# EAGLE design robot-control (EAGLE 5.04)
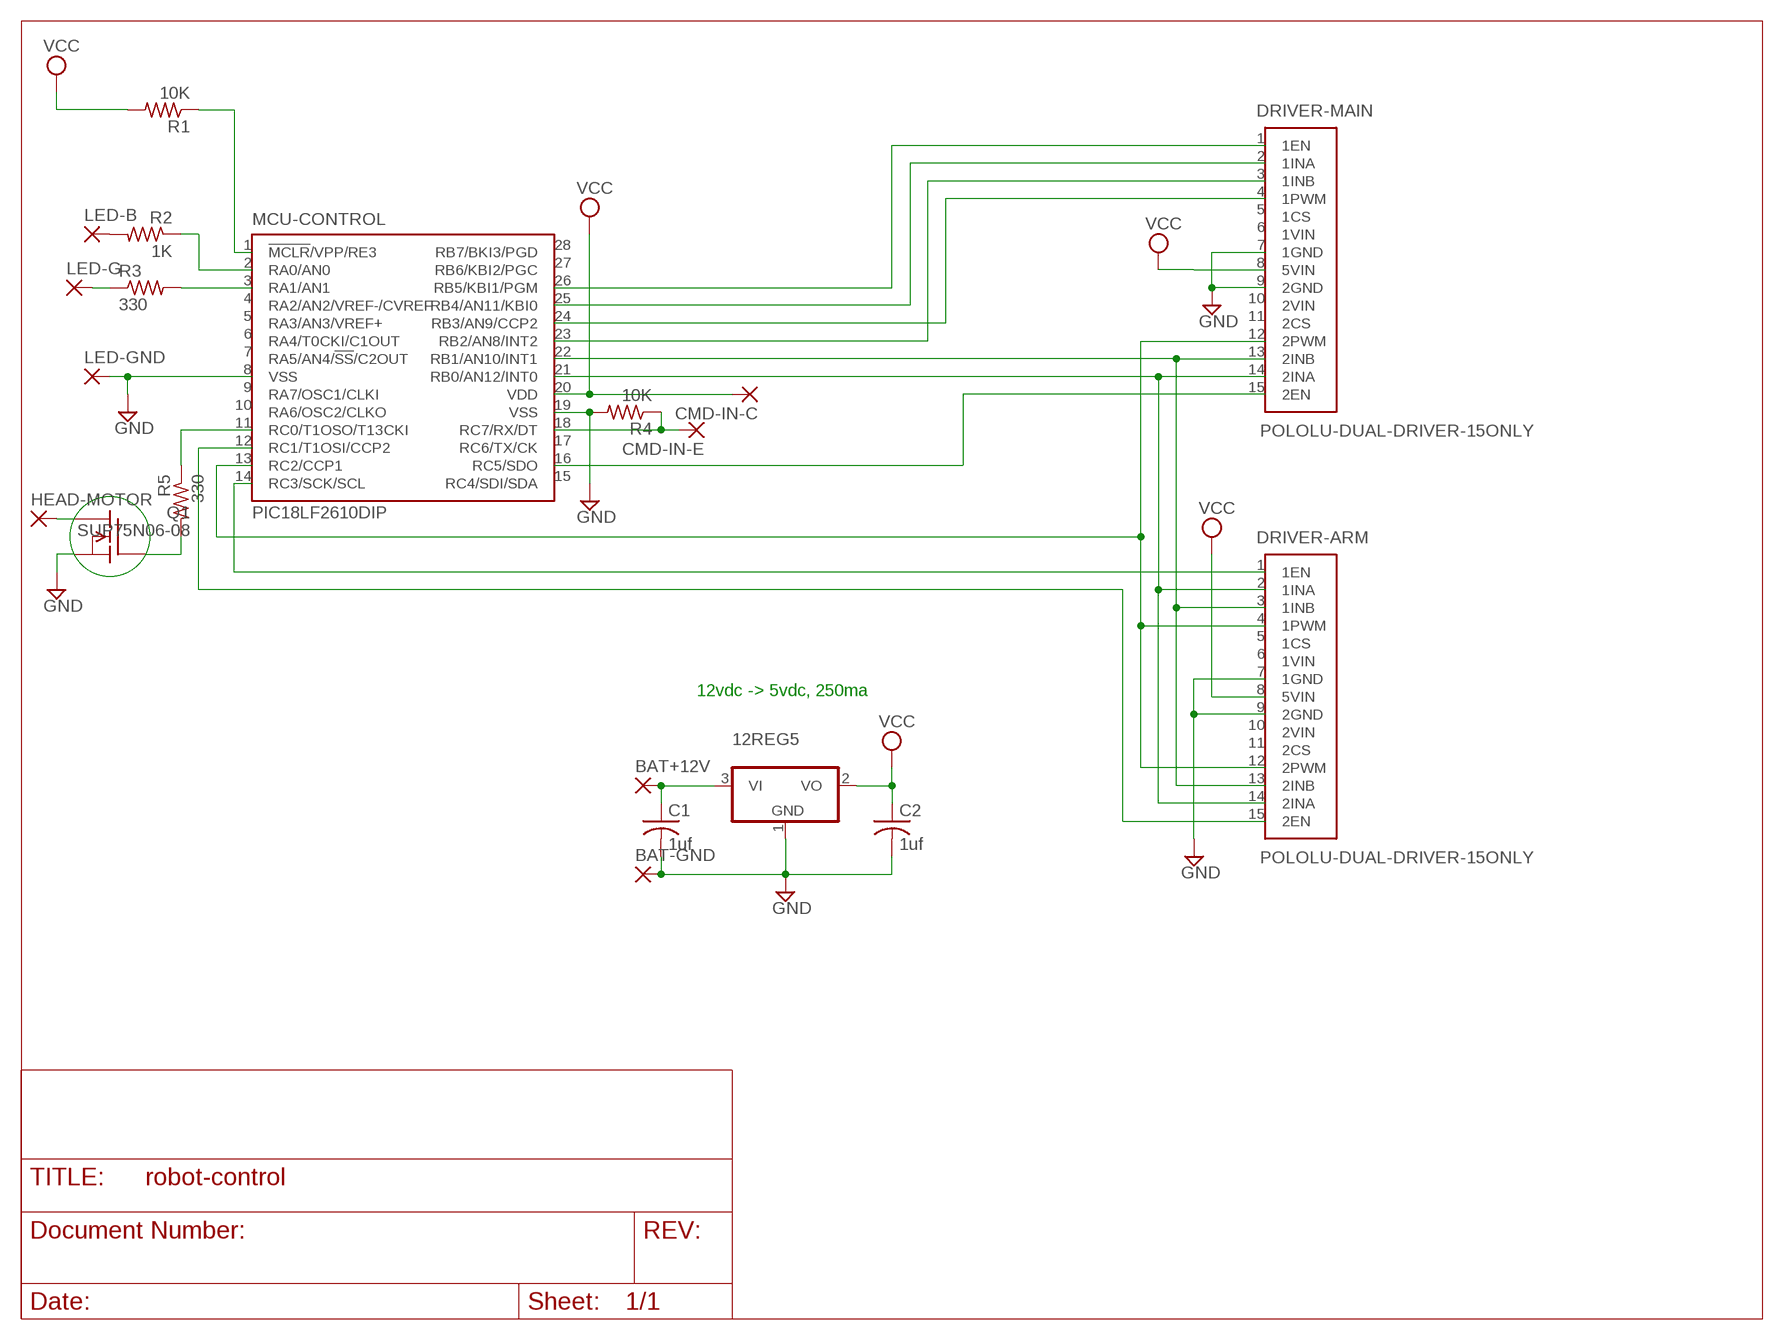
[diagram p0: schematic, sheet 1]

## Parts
12REG5  MCP1703CB  [SOT23]
BAT+12V  WIREPAD3,81/1,1  [3,81/1,1]
BAT-GND  WIREPAD3,81/1,1  [3,81/1,1]
C1  1uf  C-US025-030X050  [C025-030X050]
C2  1uf  C-US025-030X050  [C025-030X050]
CMD-IN-C  WIREPAD2,15/1,0  [2,15/1,0]
CMD-IN-E  WIREPAD2,15/1,0  [2,15/1,0]
DRIVER-ARM  POLOLU-DUAL-DRIVER-15ONLY  [15SIL]
DRIVER-MAIN  POLOLU-DUAL-DRIVER-15ONLY  [15SIL]
HEAD-MOTOR  WIREPAD3,81/1,1  [3,81/1,1]
LED-B  WIREPAD2,15/1,0  [2,15/1,0]
LED-G  WIREPAD2,15/1,0  [2,15/1,0]
LED-GND  WIREPAD2,15/1,0  [2,15/1,0]
MCU-CONTROL  PIC18LF2610DIP  [DIL28-3]
Q1  SUP75N06-08  [TO220]
R1  10K  R-US_0204/7  [0204/7]
R2  1K  R-US_0204/7  [0204/7]
R3  330  R-US_0204/7  [0204/7]
R4  10K  R-US_0204/7  [0204/7]
R5  330  R-US_0204/7  [0204/7]

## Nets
GND: 12REG5.1(GND) BAT-GND.1(P) C1.2 C2.2 DRIVER-ARM.7(1GND) DRIVER-ARM.9(2GND) DRIVER-MAIN.7(1GND) DRIVER-MAIN.9(2GND) LED-GND.1(P) MCU-CONTROL.8(VSS) MCU-CONTROL.19(VSS) Q1.3(S) R4.2
N$2: LED-B.1(P) R2.2
N$3: DRIVER-ARM.4(1PWM) DRIVER-ARM.12(2PWM) DRIVER-MAIN.12(2PWM) MCU-CONTROL.13(RC2/CCP1)
N$4: 12REG5.3(VI) BAT+12V.1(P) C1.1
N$5: MCU-CONTROL.2(RA0/AN0) R2.1
N$6: LED-G.1(P) R3.1
N$8: Q1.1(G) R5.2
N$9: CMD-IN-E.1(P) MCU-CONTROL.18(RC7/RX/DT) R4.1
N$11: HEAD-MOTOR.1(P) Q1.2(D)
N$12: DRIVER-MAIN.4(1PWM) MCU-CONTROL.24(RB3/AN9/CCP2)
N$15: DRIVER-ARM.1(1EN) MCU-CONTROL.14(RC3/SCK/SCL)
N$17: MCU-CONTROL.3(RA1/AN1) R3.2
N$18: DRIVER-ARM.2(1INA) DRIVER-ARM.14(2INA) DRIVER-MAIN.14(2INA) MCU-CONTROL.21(RB0/AN12/INT0)
N$21: DRIVER-MAIN.2(1INA) MCU-CONTROL.25(RB4/AN11/KBI0)
N$22: DRIVER-MAIN.3(1INB) MCU-CONTROL.23(RB2/AN8/INT2)
N$24: DRIVER-MAIN.15(2EN) MCU-CONTROL.16(RC5/SDO)
N$28: MCU-CONTROL.1(!MCLR!/VPP/RE3) R1.1
N$31: DRIVER-MAIN.1(1EN) MCU-CONTROL.26(RB5/KBI1/PGM)
N$33: MCU-CONTROL.11(RC0/T1OSO/T13CKI) R5.1
N$42: DRIVER-ARM.15(2EN) MCU-CONTROL.12(RC1/T1OSI/CCP2)
N$54: DRIVER-ARM.3(1INB) DRIVER-ARM.13(2INB) DRIVER-MAIN.13(2INB) MCU-CONTROL.22(RB1/AN10/INT1)
VCC: 12REG5.2(VO) C2.1 CMD-IN-C.1(P) DRIVER-ARM.8(5VIN) DRIVER-MAIN.8(5VIN) MCU-CONTROL.20(VDD) R1.2
Unconnected: DRIVER-ARM.5(1CS) DRIVER-ARM.6(1VIN) DRIVER-ARM.10(2VIN) DRIVER-ARM.11(2CS) DRIVER-MAIN.5(1CS) DRIVER-MAIN.6(1VIN) DRIVER-MAIN.10(2VIN) DRIVER-MAIN.11(2CS) MCU-CONTROL.4(RA2/AN2/VREF-/CVREF) MCU-CONTROL.5(RA3/AN3/VREF+) MCU-CONTROL.6(RA4/T0CKI/C1OUT) MCU-CONTROL.7(RA5/AN4/!SS!/C2OUT) MCU-CONTROL.9(RA7/OSC1/CLKI) MCU-CONTROL.10(RA6/OSC2/CLKO) MCU-CONTROL.15(RC4/SDI/SDA) MCU-CONTROL.17(RC6/TX/CK) MCU-CONTROL.27(RB6/KBI2/PGC) MCU-CONTROL.28(RB7/BKI3/PGD)

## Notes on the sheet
- 12vdc -> 5vdc, 250ma

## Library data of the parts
12REG5 = linear:MCP1703: 250 mA, 16V, Low Quiescent Current LDO Regulator Source: http://ww1.microchip.com/downloads/en/DeviceDoc/22049b.pdf
BAT+12V BAT-GND CMD-IN-C CMD-IN-E HEAD-MOTOR LED-B LED-G LED-GND = wirepad:WIREPAD: Wire PAD connect wire on PCB
C1 C2 = rcl:C-US: CAPACITOR, American symbol
DRIVER-ARM DRIVER-MAIN = trl:POLOLU-DUAL-DRIVER-15ONLY
MCU-CONTROL = trl:PIC18LF2610: PIC18LF2610 28-Pin, No USB or EEPROM
Q1 = transistor-fet:SUP75N06-08: N-Channel Enhancement MOSFET 60V; 75A; 0,008Ohm
R1-R5 = resistor:R-US_: RESISTOR, American symbol

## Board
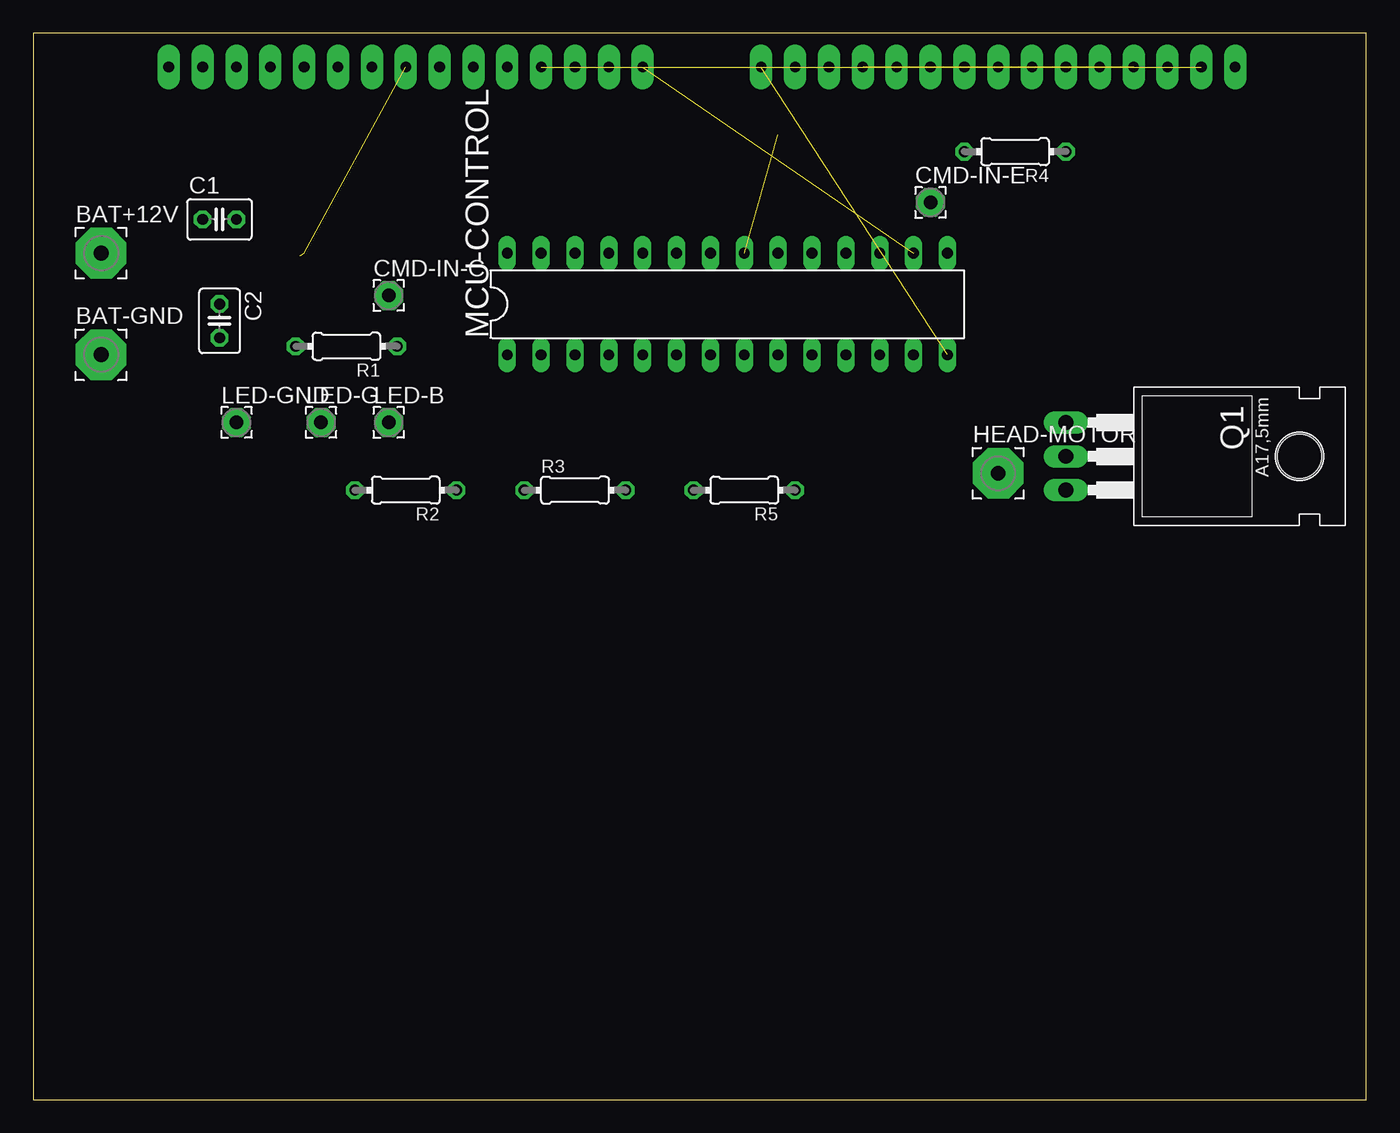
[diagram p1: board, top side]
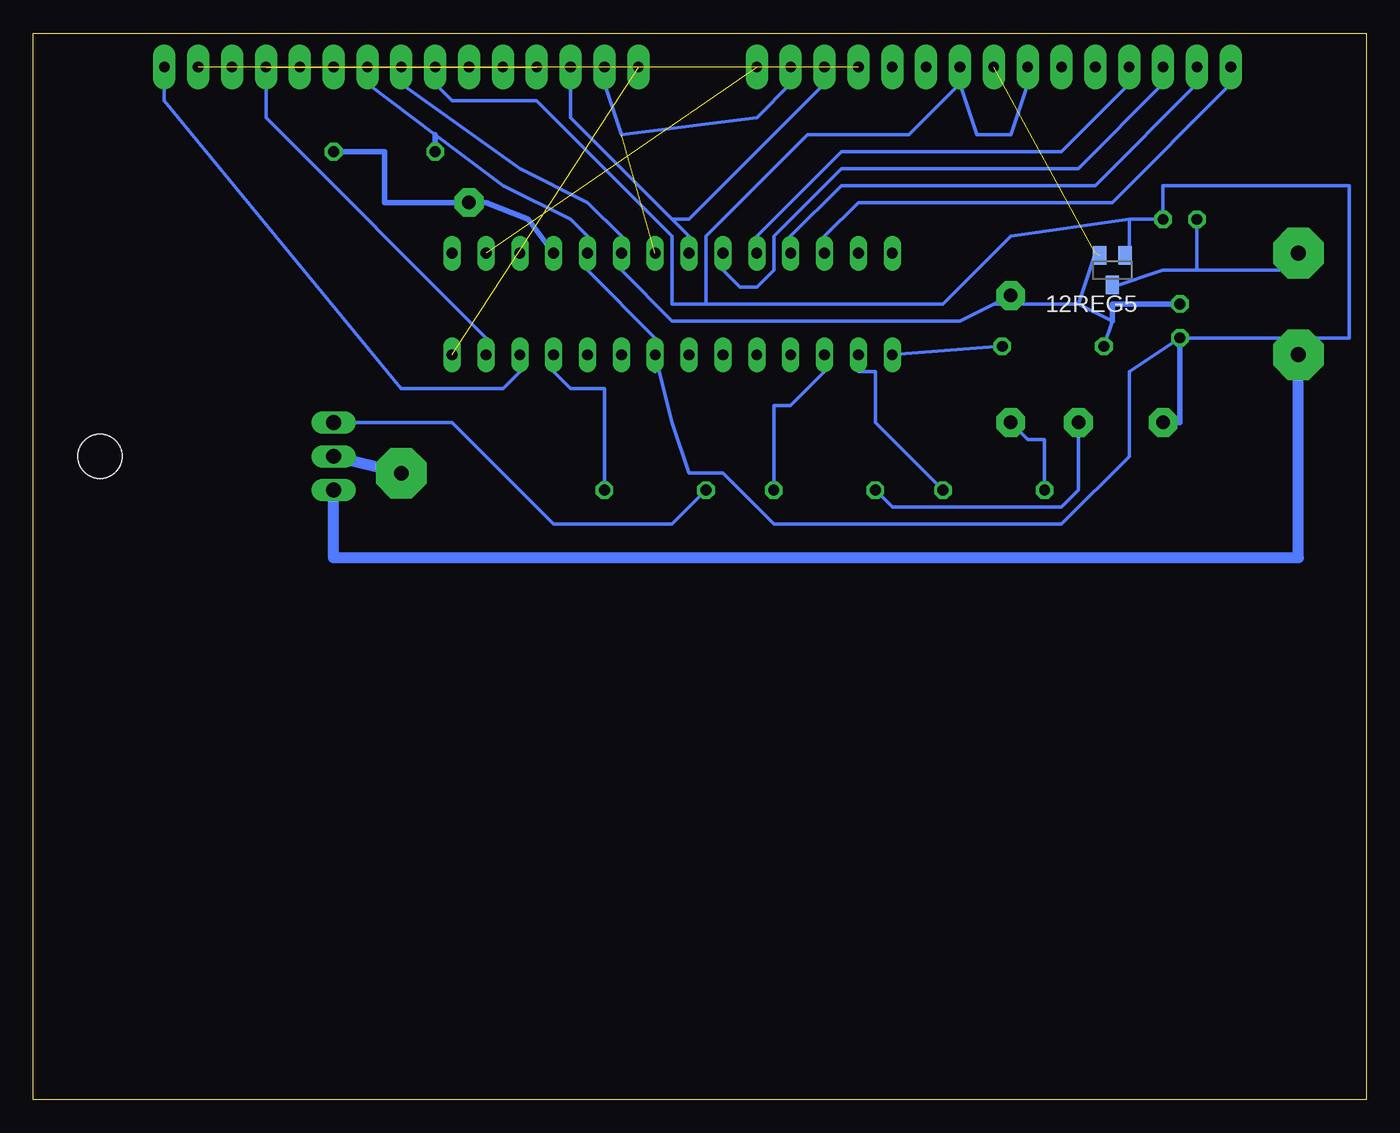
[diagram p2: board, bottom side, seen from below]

Size 100 x 80 mm. Coordinates in mm from the lower left corner, seen from the top.
Outline: 0,0 100,0 100,80 0,80 0,0
Copper layers (1*16): Top 0.035mm / dielectric 1.5mm / Bottom 0.035mm
Design rules "default": minimum track width 10mil, minimum drill 24mil, track to track 8mil, track to pad 8mil, pad to pad 8mil, via to via 8mil, smd to smd 8mil, copper to edge 40mil, drill to drill 8mil, minimum pad ring 10mil, minimum via ring 8mil, stop-mask expansion 4mil, vias tented up to drill 0mil, thermal gap 10mil

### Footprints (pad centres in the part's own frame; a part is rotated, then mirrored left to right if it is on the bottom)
SOT23 = smd 1 x 1.4: 1 -0.95,-1.1; 2 0.95,-1.1; 3 0,1.1
3,81/1,1 = drill 1.118 pad 3.81 octagon: 1 0,0
C025-030X050 = drill 0.813 octagon: 1 -1.27,0; 2 1.27,0
2,15/1,0 = drill 1.016 pad 2.159 octagon: 1 0,0
15SIL = drill 0.8 pad 1.676 long: 1 -17.78,0; 2 -15.24,0; 3 -12.7,0; 4 -10.16,0; 5 -7.62,0; 6 -5.08,0; 7 -2.54,0; 8 0,0; 9 2.54,0; 10 5.08,0; 11 7.62,0; 12 10.16,0; 13 12.7,0; 14 15.24,0; 15 17.78,0
DIL28-3 = drill 0.813 long: 1 -16.51,-3.81; 2 -13.97,-3.81; 3 -11.43,-3.81; 4 -8.89,-3.81; 5 -6.35,-3.81; 6 -3.81,-3.81; 7 -1.27,-3.81; 8 1.27,-3.81; 9 3.81,-3.81; 10 6.35,-3.81; 11 8.89,-3.81; 12 11.43,-3.81; 13 13.97,-3.81; 14 16.51,-3.81; 15 16.51,3.81; 16 13.97,3.81; 17 11.43,3.81; 18 8.89,3.81; 19 6.35,3.81; 20 3.81,3.81; 21 1.27,3.81; 22 -1.27,3.81; 23 -3.81,3.81; 24 -6.35,3.81; 25 -8.89,3.81; 26 -11.43,3.81; 27 -13.97,3.81; 28 -16.51,3.81
TO220 = drill 1.118 long: 1 -2.54,-6.35; 2 0,-6.35; 3 2.54,-6.35 | hole 3.302: 0,11.176
0204/7 = drill 0.813 octagon: 1 -3.81,0; 2 3.81,0

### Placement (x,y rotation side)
12REG5  19.05,62.23 180 bottom
BAT+12V  5.08,63.5 0 top
BAT-GND  5.08,55.88 0 top
C1  13.97,66.04 0 top
C2  13.97,58.42 270 top
CMD-IN-C  26.67,60.33 0 top
CMD-IN-E  67.31,67.31 0 top
DRIVER-ARM  72.39,77.47 0 top
DRIVER-MAIN  27.94,77.47 0 top
HEAD-MOTOR  72.39,46.99 0 top
LED-B  26.67,50.8 0 top
LED-G  21.59,50.8 0 top
LED-GND  15.24,50.8 0 top
MCU-CONTROL  52.07,59.69 0 top
Q1  83.82,48.26 270 top
R1  23.5,56.52 180 top
R2  27.94,45.72 180 top
R3  40.64,45.72 0 top
R4  73.66,71.12 180 top
R5  53.34,45.72 180 top

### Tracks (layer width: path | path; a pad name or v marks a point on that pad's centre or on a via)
GND
  Bottom 0.254: MCU-CONTROL.8 53.34,57.15 58.42,62.23 MCU-CONTROL.19 58.42,64.77 59.69,66.04 64.77,68.58 69.85,72.39 74.93,76.2 DRIVER-ARM.9 | MCU-CONTROL.8 53.34,54.61 | 30.48,76.2 29.21,72.39 26.67,72.39 25.4,76.2 DRIVER-MAIN.7 | 30.48,76.2 DRIVER-MAIN.9 30.48,76.2 | 17.78,66.04 17.78,63.5 12REG5.1 | 17.78,66.04 C1.2 15.24,68.58 1.27,68.58 1.27,57.15 3.81,57.15 BAT-GND.1 6.35,57.15 C2.2 17.78,54.61 17.78,48.26 22.86,43.18 44.45,43.18 48.26,46.99 50.8,46.99 52.07,50.8 MCU-CONTROL.8 | 49.53,59.69 31.75,59.69 26.67,64.77 17.78,66.04 | 49.53,59.69 52.07,59.69 52.07,64.77 62.23,74.93 68.58,74.93 69.85,76.2 DRIVER-ARM.7 | 30.48,76.2 34.29,72.39 41.91,72.39 49.53,64.77 49.53,59.69
  Bottom 0.406: LED-GND.1 13.97,50.8 C2.2 | 69.85,72.39 R4.2
  Bottom 0.813: BAT-GND.1 5.08,40.64 16.51,40.64 77.47,40.64 Q1.3
N$2
  Bottom 0.254: R2.2 24.13,49.53 25.4,49.53 LED-B.1
N$3  (2 unrouted)
  Bottom 0.254: MCU-CONTROL.13 66.04,57.15 82.55,73.66 82.55,76.2 DRIVER-ARM.12
N$4
  Bottom 0.254: 12.7,62.23 6.35,62.23 BAT+12V.1 | 12.7,62.23 15.24,62.23 19.05,60.96 12REG5.3 | 12.7,62.23 C1.1
N$5
  Bottom 0.254: R2.1 36.83,50.8 36.83,54.61 38.1,54.61 MCU-CONTROL.2
N$6
  Bottom 0.254: R3.1 35.56,44.45 22.86,44.45 21.59,45.72 21.59,49.53 LED-G.1
N$8
  Bottom 0.254: R5.2 52.07,43.18 60.96,43.18 68.58,50.8 Q1.1
N$9
  Bottom 0.406: MCU-CONTROL.18 62.87,66.04 66.04,67.31 | 66.04,67.31 CMD-IN-E.1 | 66.04,67.31 73.66,67.31 73.66,71.12 R4.1
N$11
  Bottom 0.813: HEAD-MOTOR.1 Q1.2
N$12
  Bottom 0.254: MCU-CONTROL.24 45.72,64.77 39.37,71.12 22.86,71.12 17.78,76.2 DRIVER-MAIN.4
N$15  (1 unrouted)
N$17
  Bottom 0.254: R3.2 44.45,52.07 43.18,52.07 40.64,54.61 MCU-CONTROL.3
N$18  (2 unrouted)
  Bottom 0.254: DRIVER-MAIN.14 43.18,76.2 45.72,73.66 55.88,72.39 57.15,76.2 DRIVER-ARM.2
N$21
  Bottom 0.254: MCU-CONTROL.25 43.18,64.77 39.37,68.58 20.32,68.58 12.7,76.2 DRIVER-MAIN.2
N$22
  Bottom 0.254: MCU-CONTROL.23 48.26,62.23 46.99,60.96 45.72,60.96 44.45,62.23 44.45,64.77 39.37,69.85 21.59,69.85 15.24,76.2 DRIVER-MAIN.3
N$24  (1 unrouted)
N$28
  Bottom 0.254: R1.1 MCU-CONTROL.1
N$31
  Bottom 0.254: MCU-CONTROL.26 40.64,64.77 38.1,67.31 19.05,67.31 10.16,76.2 DRIVER-MAIN.1
N$33
  Bottom 0.254: R5.1 57.15,53.34 59.69,53.34 60.96,54.61 MCU-CONTROL.11
N$42
  Bottom 0.254: MCU-CONTROL.12 63.5,54.61 64.77,53.34 72.39,53.34 90.17,74.93 90.17,76.2 DRIVER-ARM.15
N$54  (1 unrouted)
  Bottom 0.254: 52.07,66.04 59.69,73.66 59.69,76.2 DRIVER-ARM.3 | 52.07,66.04 50.8,64.77 MCU-CONTROL.22 | 52.07,66.04 50.8,66.04 40.64,76.2 DRIVER-MAIN.13
VCC  (2 unrouted)
  Bottom 0.254: 21.59,59.69 20.32,63.5 | 21.59,59.69 19.05,58.42 R1.2 | 27.94,59.69 CMD-IN-C.1 27.94,59.69 | 27.94,59.69 30.48,58.42 52.07,58.42 55.88,62.23 MCU-CONTROL.20 55.88,64.77 58.42,67.31 63.5,69.85 72.39,76.2 DRIVER-ARM.8 | 21.59,59.69 27.94,59.69
  Bottom 0.406: C2.1 19.05,59.69 19.05,58.42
